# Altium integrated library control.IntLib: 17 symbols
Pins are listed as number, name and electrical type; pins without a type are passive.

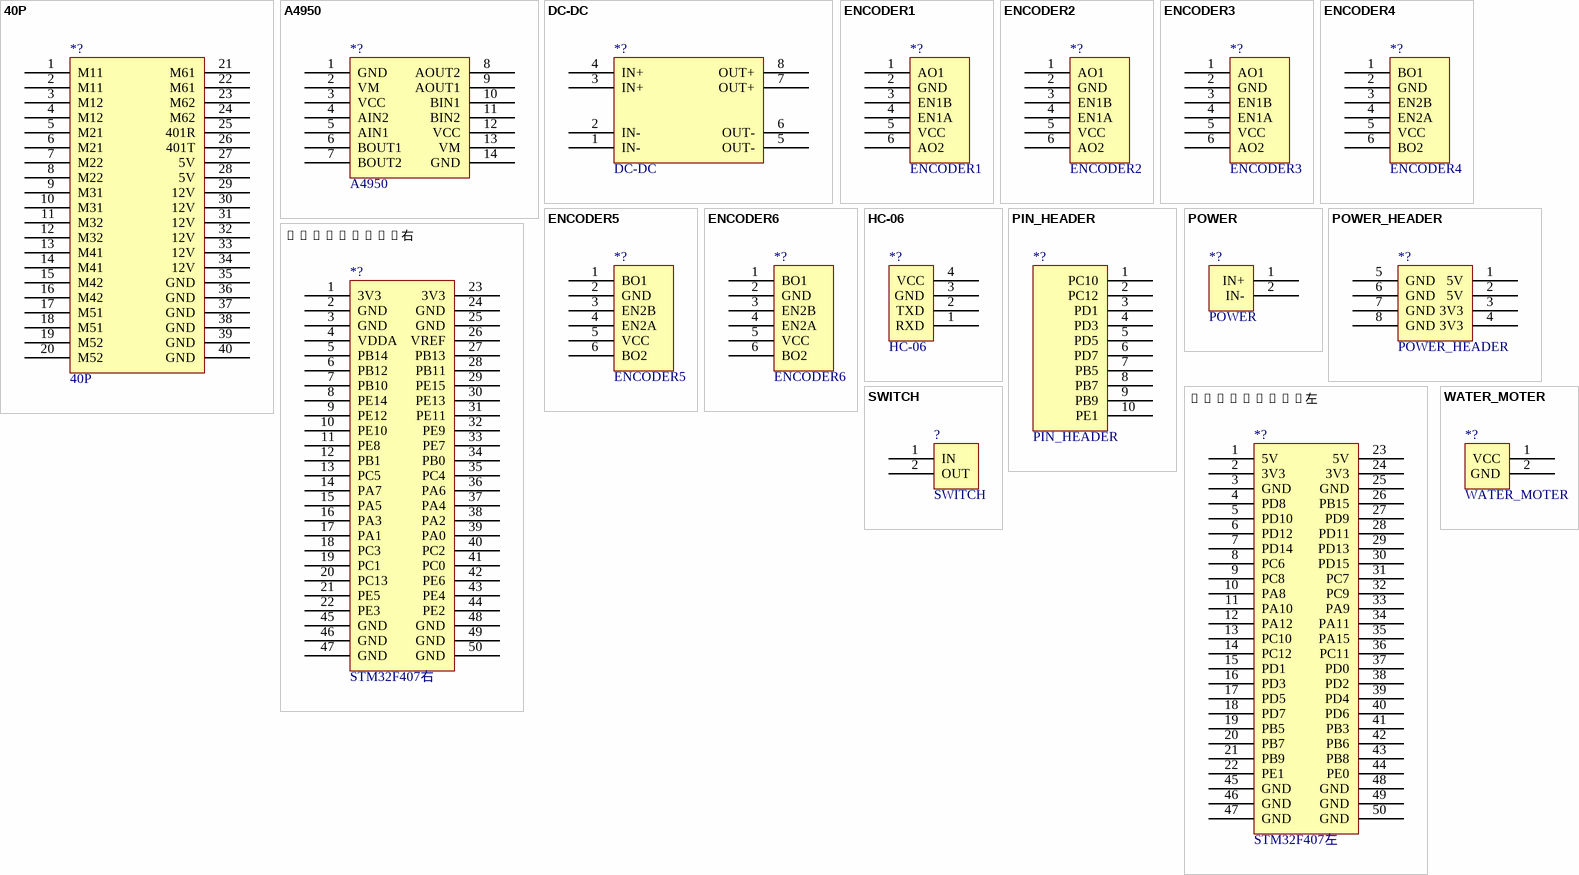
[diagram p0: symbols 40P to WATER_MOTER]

## 40P
designator *?
footprint PCBComponent_1
pins: 1 M11, 2 M11, 3 M12, 4 M12, 5 M21, 6 M21, 7 M22, 8 M22, 9 M31, 10 M31, 11 M32, 12 M32, 13 M41, 14 M41, 15 M42, 16 M42, 17 M51, 18 M51, 19 M52, 20 M52, 21 M61, 22 M61, 23 M62, 24 M62, 25 401R, 26 401T, 27 5V, 28 5V, 29 12V, 30 12V, 31 12V, 32 12V, 33 12V, 34 12V, 35 GND, 36 GND, 37 GND, 38 GND, 39 GND, 40 GND

## A4950
designator *?
footprint A4950
pins: 1 GND, 2 VM, 3 VCC, 4 AIN2, 5 AIN1, 6 BOUT1, 7 BOUT2, 8 AOUT2, 9 AOUT1, 10 BIN1, 11 BIN2, 12 VCC, 13 VM, 14 GND

## DC-DC
designator *?
footprint DC-DC
pins: 1 IN-, 2 IN-, 3 IN+, 4 IN+, 5 OUT-, 6 OUT-, 7 OUT+, 8 OUT+

## ENCODER1
designator *?
footprint ENCODER1
pins: 1 AO1, 2 GND, 3 EN1B, 4 EN1A, 5 VCC, 6 AO2

## ENCODER2
designator *?
footprint ENCODER1
pins: 1 AO1, 2 GND, 3 EN1B, 4 EN1A, 5 VCC, 6 AO2

## ENCODER3
designator *?
footprint ENCODER1
footprint ENCODER1
pins: 1 AO1, 2 GND, 3 EN1B, 4 EN1A, 5 VCC, 6 AO2

## ENCODER4
designator *?
footprint ENCODER2
pins: 1 BO1, 2 GND, 3 EN2B, 4 EN2A, 5 VCC, 6 BO2

## ENCODER5
designator *?
footprint ENCODER2
pins: 1 BO1, 2 GND, 3 EN2B, 4 EN2A, 5 VCC, 6 BO2

## ENCODER6
designator *?
footprint ENCODER2
pins: 1 BO1, 2 GND, 3 EN2B, 4 EN2A, 5 VCC, 6 BO2

## HC-06
designator *?
footprint HC-06
pins: 1 RXD, 2 TXD, 3 GND, 4 VCC

## PIN_HEADER
designator *?
footprint PIN_HEADER
pins: 1 PC10, 2 PC12, 3 PD1, 4 PD3, 5 PD5, 6 PD7, 7 PB5, 8 PB7, 9 PB9, 10 PE1

## POWER
designator *?
footprint POWER
pins: 1 IN+, 2 IN-

## POWER_HEADER
designator *?
footprint POWER_HEADER
pins: 1 5V, 2 5V, 3 3V3, 4 3V3, 5 GND, 6 GND, 7 GND, 8 GND

## STM32F407右
designator *?
footprint STM32F407左
pins: 1 3V3, 2 GND, 3 GND, 4 VDDA, 5 PB14, 6 PB12, 7 PB10, 8 PE14, 9 PE12, 10 PE10, 11 PE8, 12 PB1, 13 PC5, 14 PA7, 15 PA5, 16 PA3, 17 PA1, 18 PC3, 19 PC1, 20 PC13, 21 PE5, 22 PE3, 23 3V3, 24 GND, 25 GND, 26 VREF, 27 PB13, 28 PB11, 29 PE15, 30 PE13, 31 PE11, 32 PE9, 33 PE7, 34 PB0, 35 PC4, 36 PA6, 37 PA4, 38 PA2, 39 PA0, 40 PC2, 41 PC0, 42 PE6, 43 PE4, 44 PE2, 45 GND, 46 GND, 47 GND, 48 GND, 49 GND, 50 GND

## STM32F407左
designator *?
footprint STM32F407左
pins: 1 5V, 2 3V3, 3 GND, 4 PD8, 5 PD10, 6 PD12, 7 PD14, 8 PC6, 9 PC8, 10 PA8, 11 PA10, 12 PA12, 13 PC10, 14 PC12, 15 PD1, 16 PD3, 17 PD5, 18 PD7, 19 PB5, 20 PB7, 21 PB9, 22 PE1, 23 5V, 24 3V3, 25 GND, 26 PB15, 27 PD9, 28 PD11, 29 PD13, 30 PD15, 31 PC7, 32 PC9, 33 PA9, 34 PA11, 35 PA15, 36 PC11, 37 PD0, 38 PD2, 39 PD4, 40 PD6, 41 PB3, 42 PB6, 43 PB8, 44 PE0, 45 GND, 46 GND, 47 GND, 48 GND, 49 GND, 50 GND

## SWITCH
designator ?
footprint switch
pins: 1 IN, 2 OUT

## WATER_MOTER
designator *?
footprint WATER_HEADER
pins: 1 VCC, 2 GND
